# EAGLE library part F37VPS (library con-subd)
SUB-D
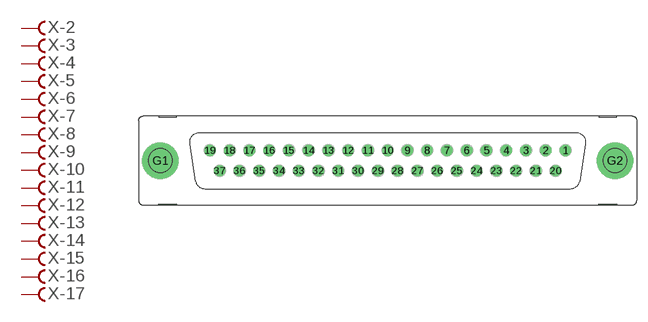
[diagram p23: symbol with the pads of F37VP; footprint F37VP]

Designator prefix X; gates -2=F -3=F -4=F -5=F -6=F -7=F -8=F -9=F -10=F -11=F -12=F -13=F -14=F -15=F -16=F -17=F -18=F -19=F -20=F -21=F -22=F -23=F -24=F -25=F -26=F -27=F -28=F -29=F -30=F -31=F -32=F -33=F -34=F -35=F -36=F -37=F -G=GND -1=FV

## F37VPS (OC_FARNELL: unknown; OC_NEWARK: unknown)  [F37VP]
1  -1:F  pas
2  -2:F  pas
3  -3:F  pas
4  -4:F  pas
5  -5:F  pas
6  -6:F  pas
7  -7:F  pas
8  -8:F  pas
9  -9:F  pas
10  -10:F  pas
11  -11:F  pas
12  -12:F  pas
13  -13:F  pas
14  -14:F  pas
15  -15:F  pas
16  -16:F  pas
17  -17:F  pas
18  -18:F  pas
19  -19:F  pas
20  -20:F  pas
21  -21:F  pas
22  -22:F  pas
23  -23:F  pas
24  -24:F  pas
25  -25:F  pas
26  -26:F  pas
27  -27:F  pas
28  -28:F  pas
29  -29:F  pas
30  -30:F  pas
31  -31:F  pas
32  -32:F  pas
33  -33:F  pas
34  -34:F  pas
35  -35:F  pas
36  -36:F  pas
37  -37:F  pas
G1  -G:G1  pas
G2  -G:G2  pas

## Footprint F37VP (pad centres in mm)
SUB-D
drill 1.016 octagon: 1 24.841,1.422; 2 22.073,1.422; 3 19.329,1.422; 4 16.561,1.422; 5 13.792,1.422; 6 11.049,1.422; 7 8.28,1.422; 8 5.512,1.422; 9 2.769,1.422; 10 0,1.422; 11 -2.769,1.422; 12 -5.512,1.422; 13 -8.28,1.422; 14 -11.049,1.422; 15 -13.818,1.422; 16 -16.561,1.422; 17 -19.329,1.422; 18 -22.098,1.422; 19 -24.841,1.422; 20 23.47,-1.422; 21 20.701,-1.422; 22 17.932,-1.422; 23 15.189,-1.422; 24 12.421,-1.422; 25 9.652,-1.422; 26 6.909,-1.422; 27 4.14,-1.422; 28 1.372,-1.422; 29 -1.372,-1.422; 30 -4.14,-1.422; 31 -6.909,-1.422; 32 -9.677,-1.422; 33 -12.421,-1.422; 34 -15.189,-1.422; 35 -17.958,-1.422; 36 -20.701,-1.422; 37 -23.47,-1.422
drill 3.302 pad 5.08 round: G1 -31.75,0; G2 31.75,0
